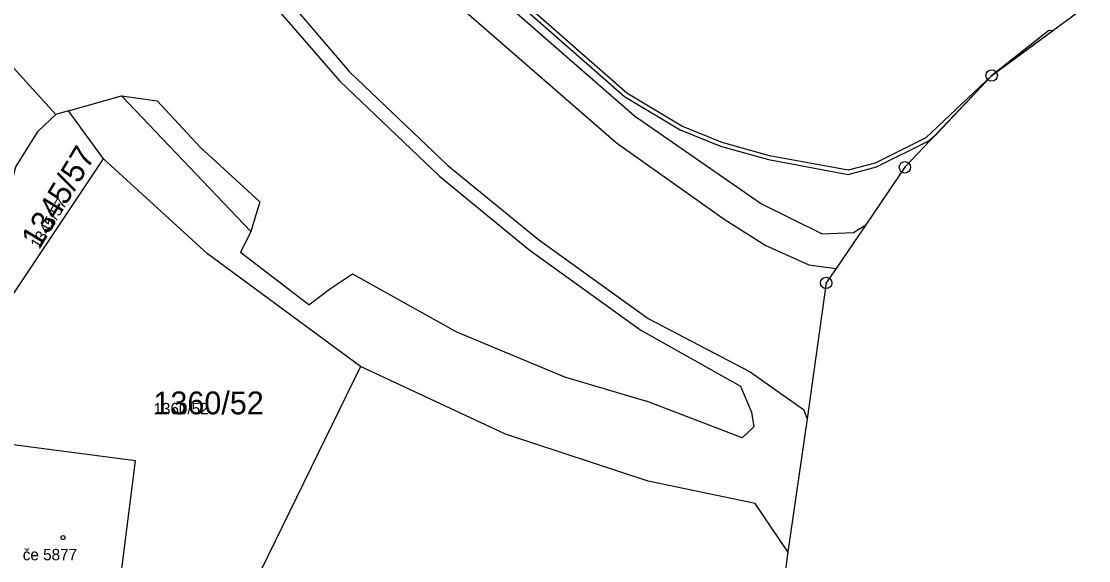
# Model space of a CAD drawing. Extents: x -763628 to -761565, y -976033 to -973833.
# Drawn here: x -762196.1 to -762102.6, y -975553 to -975505.7 of the extents above; entities that cross this region are included whole.
import ezdxf

# ---------------------------------------------------------------- set-up
doc = ezdxf.new("R2010")
doc.units = 0
for name, color, linetype in [('KN_cisla parcel 1000', 7, 'Continuous'), ('KN_cisla parcel 500', 7, 'Continuous'), ('KN_cisla popisna 500', 7, 'Continuous'), ('KN_hranice parcel', 7, 'Continuous'), ('KN_hranice uzemi', 7, 'Continuous'), ('KN_vecna bremena', 7, 'Continuous'), ('KN_vnitrni kresba parcel', 7, 'Continuous'), ('KN_znacky bodu BP', 7, 'Continuous'), ('KN_znacky budov', 7, 'Continuous')]:
    doc.layers.add(name, color=color, linetype=linetype)

msp = doc.modelspace()

# ---------------------------------------------------------------- linework, layer by layer
at = {"layer": 'KN_hranice parcel'}
for p, q in [((-762198.76, -975532.46), (-762188.95, -975517.73)), ((-762166.44, -975535.96), (-762177.94, -975559.51))]:
    msp.add_line(p, q, dxfattribs=at)
for points in [[(-762183.7, -975455.81), (-762183.1, -975458.61), (-762178.9, -975468.1), (-762175.44, -975475.16), (-762170.93, -975482.9), (-762165.9, -975490.34), (-762160.53, -975497.18), (-762155.65, -975502.39), (-762142.43, -975513.96), (-762131.28, -975521.68), (-762125.96, -975524.31), (-762123.23, -975524.21), (-762122.16, -975523.53)], [(-762193.11, -975513.85), (-762199.5, -975506.85), (-762201.33, -975504.84), (-762200.93, -975501.33), (-762202.1, -975499.73), (-762203.51, -975496.63)], [(-762198.76, -975532.46), (-762197.29, -975521.04), (-762196.62, -975518.44), (-762194.68, -975515.32), (-762193.11, -975513.85)], [(-762188.95, -975517.73), (-762192.01, -975513.54), (-762193.11, -975513.85)], [(-762166.44, -975535.96), (-762179.83, -975526.08), (-762188.95, -975517.73)], [(-762128.97, -975552.21), (-762131.84, -975547.96), (-762141.22, -975546.01), (-762153.71, -975541.88), (-762166.44, -975535.96)], [(-762186.13, -975544.23), (-762197.52, -975542.74), (-762199.92, -975561.42), (-762200.68, -975567.26), (-762192.77, -975568.3), (-762192, -975562.46), (-762188.5, -975562.92), (-762186.13, -975544.23)]]:
    msp.add_lwpolyline(points, dxfattribs=at)
at = {"layer": 'KN_hranice uzemi'}
msp.add_line((-762128.97, -975552.21), (-762131.51, -975570.95), dxfattribs=at)
for points in [[(-762058.16, -975491.03), (-762073.84, -975492.36), (-762078.87, -975493.39), (-762083.47, -975494.57), (-762090.72, -975497.24), (-762096.78, -975500.38), (-762101.28, -975503.21), (-762111.12, -975510.43), (-762118.72, -975518.48), (-762122.16, -975523.53)], [(-762122.16, -975523.53), (-762124.76, -975527.35), (-762125.63, -975528.62)], [(-762125.63, -975528.62), (-762127.3, -975540.54), (-762128.97, -975552.21)]]:
    msp.add_lwpolyline(points, dxfattribs=at)
at = {"layer": 'KN_vecna bremena'}
msp.add_lwpolyline([(-762155.35, -975501.67), (-762143.3, -975512.26), (-762138.43, -975515.18), (-762134.87, -975516.64), (-762130.68, -975517.81), (-762123.69, -975519.1), (-762121.22, -975518.43), (-762116.69, -975516.19), (-762115.94, -975515.54), (-762111.12, -975510.43), (-762116.89, -975515.89), (-762121.34, -975518.11), (-762123.71, -975518.74), (-762130.6, -975517.47), (-762134.75, -975516.3), (-762138.27, -975514.86), (-762143.1, -975511.98), (-762155.11, -975501.41)], dxfattribs=at)
msp.add_lwpolyline([(-762105.79, -975506.52), (-762106.1, -975506.48), (-762111.12, -975510.43)], close=True, dxfattribs=at)
at = {"layer": 'KN_vnitrni kresba parcel'}
for p, q in [((-762174.06, -975502.31), (-762167.38, -975510.12)), ((-762175.04, -975503.06), (-762168.26, -975510.91)), ((-762157.4, -975504.66), (-762144, -975516.34)), ((-762167.38, -975510.12), (-762158.77, -975518.33)), ((-762168.26, -975510.91), (-762159.5, -975519.26)), ((-762192.01, -975513.54), (-762187.36, -975512.22)), ((-762187.36, -975512.22), (-762184.25, -975512.65)), ((-762176.03, -975524.12), (-762187.36, -975512.22)), ((-762184.25, -975512.65), (-762180.47, -975516.72)), ((-762180.47, -975516.72), (-762175.25, -975521.5)), ((-762144, -975516.34), (-762134.46, -975523.08)), ((-762158.77, -975518.33), (-762150.82, -975524.82)), ((-762159.5, -975519.26), (-762151.69, -975525.68)), ((-762175.25, -975521.5), (-762176.03, -975524.12)), ((-762134.46, -975523.08), (-762130.9, -975525.33)), ((-762176.03, -975524.12), (-762176.93, -975525.94)), ((-762150.82, -975524.82), (-762141.21, -975531.73)), ((-762130.9, -975525.33), (-762127.13, -975527.02)), ((-762170.96, -975530.55), (-762176.93, -975525.94)), ((-762151.69, -975525.68), (-762141.85, -975532.75)), ((-762127.13, -975527.02), (-762124.76, -975527.35)), ((-762169.14, -975529.18), (-762167.12, -975527.81)), ((-762167.12, -975527.81), (-762158.01, -975532.9)), ((-762170.96, -975530.55), (-762169.14, -975529.18)), ((-762141.21, -975531.73), (-762132.27, -975536.41)), ((-762158.01, -975532.9), (-762148.56, -975536.84)), ((-762141.85, -975532.75), (-762133.12, -975537.67)), ((-762132.27, -975536.41), (-762127.61, -975539.72)), ((-762148.56, -975536.84), (-762141.36, -975538.98)), ((-762133.12, -975537.67), (-762132.16, -975539.96)), ((-762132.99, -975542.2), (-762141.36, -975538.98)), ((-762132.16, -975539.96), (-762131.97, -975541.23)), ((-762127.61, -975539.72), (-762127.3, -975540.54)), ((-762132.99, -975542.2), (-762131.97, -975541.23))]:
    msp.add_line(p, q, dxfattribs=at)
at = {"layer": 'KN_znacky bodu BP'}
for centre, radius in [((-762111.12, -975510.43), 0.5), ((-762111.12, -975510.43), 0.0303), ((-762118.72, -975518.48), 0.5), ((-762118.72, -975518.48), 0.0303), ((-762125.63, -975528.62), 0.5), ((-762125.63, -975528.62), 0.0303)]:
    msp.add_circle(centre, radius, dxfattribs=at)
at = {"layer": 'KN_znacky budov'}
msp.add_circle((-762192.497, -975550.949), 0.175, dxfattribs=at)

# ---------------------------------------------------------------- texts
at = {"layer": 'KN_cisla parcel 1000'}
msp.add_text('1345/57', height=2, rotation=59, dxfattribs=at).set_placement((-762194.561, -975525.717))
msp.add_text('1360/52', height=2, dxfattribs=at).set_placement((-762184.57, -975540.14))
at = {"layer": 'KN_cisla parcel 500'}
msp.add_text('1345/57', height=1, rotation=59, dxfattribs=at).set_placement((-762194.561, -975525.717))
msp.add_text('1360/52', height=1, dxfattribs=at).set_placement((-762184.57, -975540.14))
at = {"layer": 'KN_cisla popisna 500'}
msp.add_text('če 5877', height=1, dxfattribs=at).set_placement((-762196.021, -975552.941))

doc.saveas('drawing.dxf')
